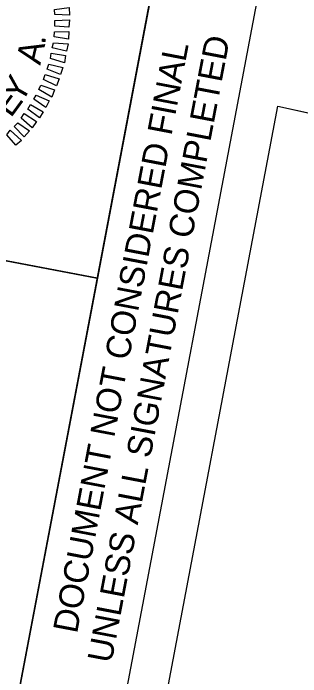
# Model space of a CAD drawing. Extents: x 1615685 to 1617075, y 899072 to 901363.
# Drawn here: x 1616128.3 to 1616192.6, y 900930.9 to 901079 of the extents above; entities that cross this region are included whole.
import ezdxf

# ---------------------------------------------------------------- set-up
doc = ezdxf.new("R2010")
doc.units = 0
for name, color, linetype in [('Default', 7, 'Continuous'), ('Exist Structure Minor Pipes CMP 15 Inch Text', 7, 'Continuous'), ('Exist Structure Minor Pipes RCP 24 Inch Text', 7, 'Continuous'), ('Prop Drainage Structure Plot Symbol 20 Scale', 7, 'Continuous'), ('Scratch_Level_8', 7, 'Continuous')]:
    doc.layers.add(name, color=color, linetype=linetype)

msp = doc.modelspace()

# ---------------------------------------------------------------- linework, layer by layer
at = {"layer": 'Default'}
for points in [[(1616137.56, 901079.86), (1616140.86, 901080.34), (1616140.88, 901078.6), (1616137.6, 901078.78)], [(1616137.64, 901077.4), (1616140.93, 901077.58), (1616140.76, 901075.93), (1616137.6, 901076.14)], [(1616137.56, 901074.92), (1616140.73, 901074.97), (1616140.71, 901073.29), (1616137.49, 901073.76)], [(1616137.34, 901072.47), (1616140.6, 901072.19), (1616140.23, 901070.58), (1616137.06, 901071.3)], [(1616136.83, 901070.12), (1616140.04, 901069.6), (1616139.78, 901067.97), (1616136.65, 901068.93)], [(1616136.31, 901067.68), (1616139.42, 901066.92), (1616138.91, 901065.34), (1616135.93, 901066.53)], [(1616135.45, 901065.4), (1616138.57, 901064.38), (1616138.01, 901062.81), (1616135.08, 901064.25)], [(1616134.52, 901062.98), (1616137.58, 901061.93), (1616136.96, 901060.32), (1616134.08, 901062)], [(1616133.48, 901060.74), (1616136.39, 901059.46), (1616135.6, 901058.03), (1616132.94, 901059.83)], [(1616132.16, 901058.7), (1616135.05, 901057.02), (1616134.23, 901055.7), (1616131.6, 901057.64)], [(1616130.79, 901056.63), (1616133.56, 901054.87), (1616132.57, 901053.48), (1616130.09, 901055.64)], [(1616129.32, 901054.57), (1616131.93, 901052.79), (1616130.75, 901051.44), (1616128.55, 901053.75)], [(1616127.67, 901052.91), (1616130.14, 901050.64), (1616128.91, 901049.56), (1616126.86, 901051.89)]]:
    msp.add_lwpolyline(points, close=True, dxfattribs=at)
at = {"layer": 'Exist Structure Minor Pipes CMP 15 Inch Text'}
for p, q in [((1616128.49, 900921.6), (1616165.81, 901118.12)), ((1616128.49, 900921.6), (1616165.81, 901118.12)), ((1616188.9, 901113.74), (1616151.58, 900917.21)), ((1616188.9, 901113.74), (1616151.58, 900917.21))]:
    msp.add_line(p, q, dxfattribs=at)
at = {"layer": 'Exist Structure Minor Pipes RCP 24 Inch Text'}
msp.add_line((1616187.49, 901058.27), (1617032.97, 900874.07), dxfattribs=at)
at = {"layer": 'Prop Drainage Structure Plot Symbol 20 Scale'}
msp.add_lwpolyline([(1616187.49, 901058.27), (1617032.97, 900874.07), (1617012.18, 900781.12), (1616950.6, 900773.34), (1616752.73, 900760.58), (1616722.43, 900593.62), (1616951.14, 900496.73), (1616753.23, 899510.43), (1615915.8, 899646.19), (1615751.76, 899738.03), (1615999.36, 900929.08), (1616157.93, 900902)], close=True, dxfattribs=at)
at = {"layer": 'Scratch_Level_8'}
msp.add_line((1616036.64, 901040.86), (1616147.13, 901019.89), dxfattribs=at)
for points in [[(1616036.64, 901040.86), (1616055.28, 901139.09), (1616165.82, 901118.12), (1616147.18, 901019.87)], [(1616770.16, 899476.57), (1615738.61, 899672.4), (1615981.06, 900949.58), (1616128.49, 900921.6), (1616165.82, 901118.12), (1617049.96, 900950.25)], [(1616017.98, 900942.57), (1616036.64, 901040.86), (1616147.18, 901019.87), (1616128.49, 900921.6)]]:
    msp.add_lwpolyline(points, close=True, dxfattribs=at)

# ---------------------------------------------------------------- texts
at = {"layer": 'Default'}
for s, rotation, p in [('.', 84.7663, (1616135.47, 901071.92)), ('A', 76.7314, (1616134.36, 901067.32)), ('Y', 60.315, (1616130.17, 901058.64)), ('E', 53.6667, (1616127.79, 901055.53))]:
    msp.add_text(s, height=5.6, rotation=rotation, dxfattribs=at).set_placement(p)
at = {"layer": 'Exist Structure Minor Pipes CMP 15 Inch Text'}
for s, p in [('UNLESS ALL SIGNATURES COMPLETED', (1616150.29, 900933.74)), ('UNLESS ALL SIGNATURES COMPLETED', (1616150.29, 900933.74)), ('DOCUMENT NOT CONSIDERED FINAL', (1616142.59, 900940.37)), ('DOCUMENT NOT CONSIDERED FINAL', (1616142.59, 900940.37))]:
    msp.add_text(s, height=5.5, rotation=79.2494, dxfattribs=at).set_placement(p)

doc.saveas('drawing.dxf')
